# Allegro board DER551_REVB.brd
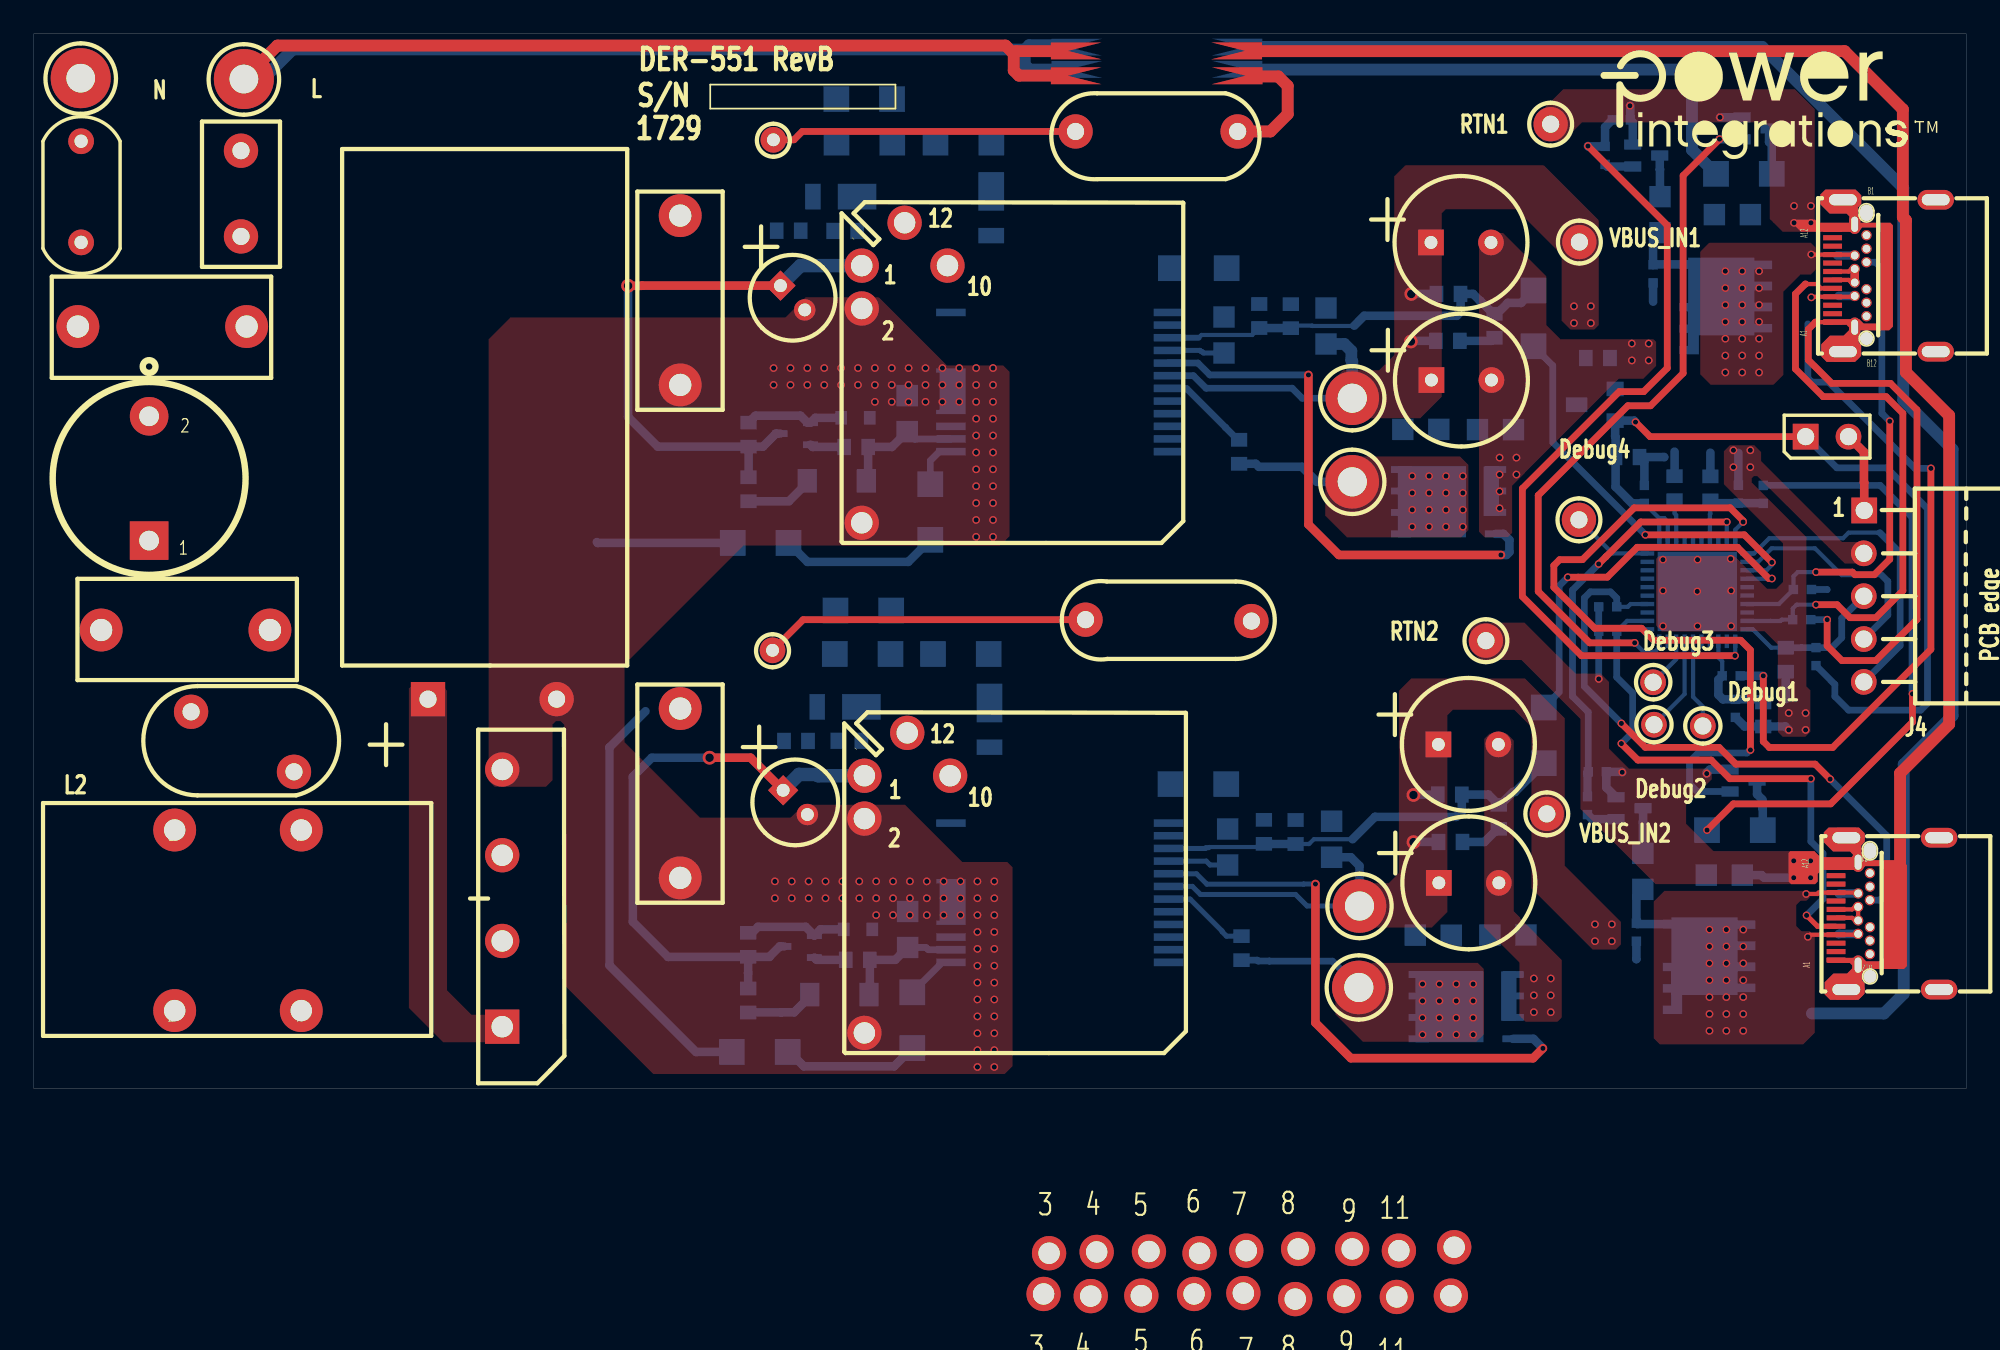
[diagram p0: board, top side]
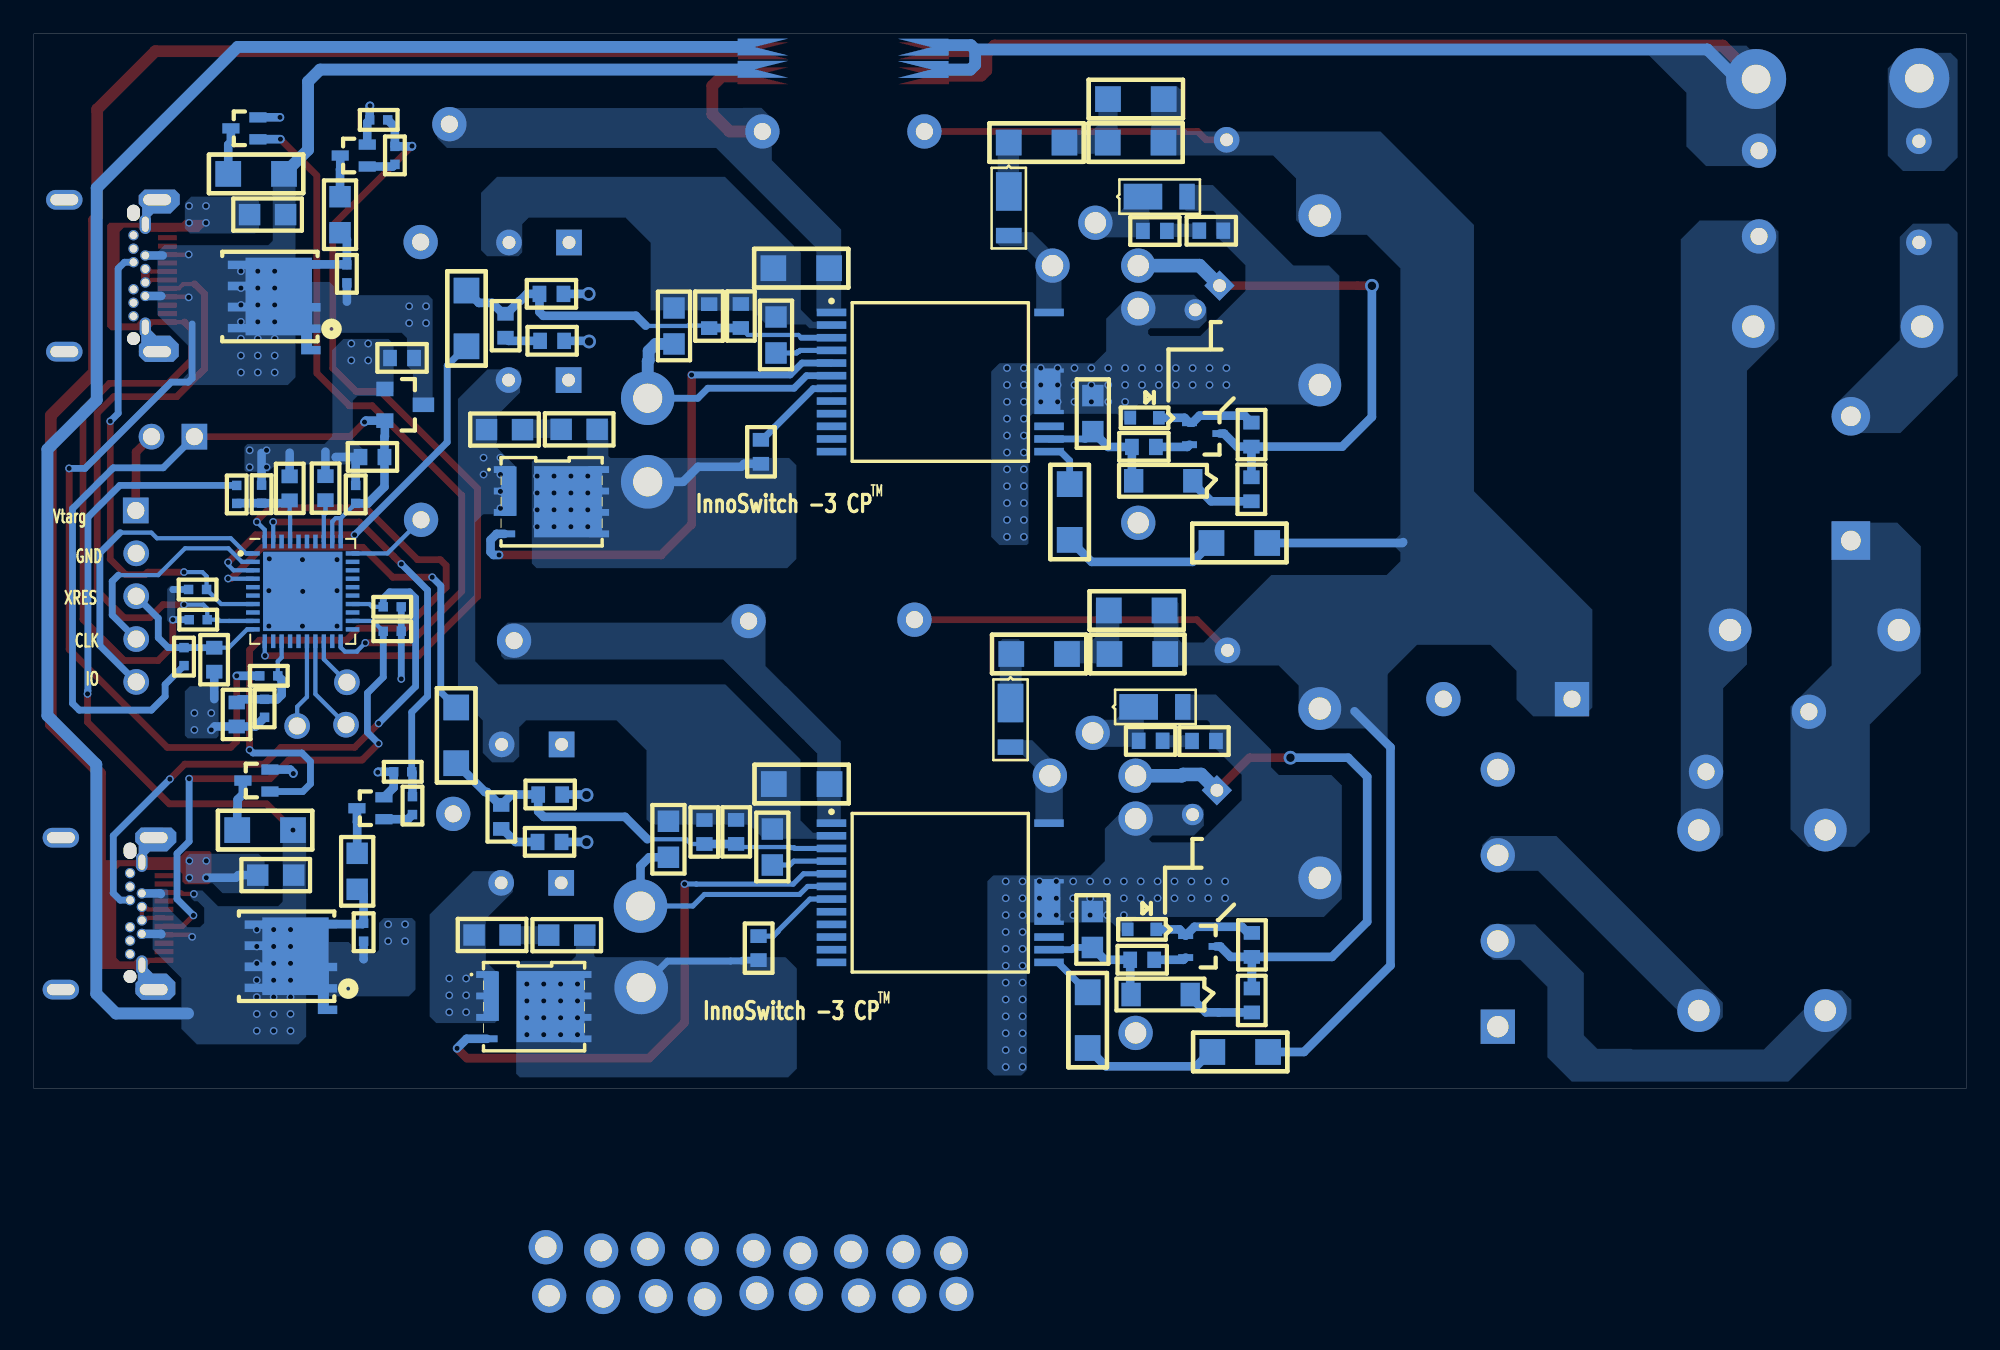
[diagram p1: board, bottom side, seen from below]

Outline 114.5 x 62.5 mm; copper layers: TOP, BOTTOM. Coordinates in mm from the lower left corner of the outline.
Outline path: 0,62.5 114.5,62.5 114.5,0 0,0 0,62.5

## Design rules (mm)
constraint set DEFAULT: min track width 0.508

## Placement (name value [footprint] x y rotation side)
BR1  GBL06  [PIDAXBRIDGEGBL06]  27.76 3.66 90 top
C1  1 nF  [PINPYCAPRAD540X290LS400040#2]  61.73 56.71 0 top
C2  470 uF  [PIPOLCAPCLYD320LS140030]  82.79 50.13 0 top
C3  470 uF  [PIPOLCAPCLYD320LS140030]  82.81 41.98 0 top
C4  2.2 nF  [PISMC1206]  50.85 58.63 180 bottom
C5  4.7 nF  [PISMC0603]  83.08 44.3 0 bottom
C6  1 nF  [PISMC0805]  85.54 39.04 0 bottom
C7  100 uF  [PIPOLCAPCLYD630LS300040]  23.36 23.07 0 top
C8  100 nF  [PI_NP_XCAP_RAD512X197X395D040]  38.3 51.72 270 top
C9  56 pF  [PISMC0603]  45.44 50.83 180 bottom
C10  100 nF  [PI_NP_CAP492X236LS394D040]  12.61 45.15 180 top
C11  2.2 uF  [PISMC0805]  70.52 45.72 270 bottom
C12  2.2 uF  [PISMC0805]  76.57 46.25 270 bottom
C13  100 nF  [PI_NP_CAP492X236LS394D040]  13.99 27.17 180 top
C14  22  uF  [PIPOLCAPCLYD200LS80030]  44.24 47.57 315 top
C15  330 pF  [PISMC0603]  72.61 45.06 90 bottom
C16  4.7 uF  [PISMC0805]  51.75 38.93 90 bottom
C17  1 nF  [PINPYCAPRAD540X290LS400040]  62.32 27.78 0 top
C18  470 uF  [PIPOLCAPCLYD320LS140030]  83.25 12.18 0 top
C19  470 uF  [PIPOLCAPCLYD320LS140030]  83.22 20.39 0 top
C20  2.2 nF  [PISMC1206]  50.8 28.33 180 bottom
C21  4.7 nF  [PISMC0603]  83.23 14.61 0 bottom
C22  1 nF  [PISMC0805]  86.28 9.1 0 bottom
C23  56 pF  [PISMC0603]  45.87 20.59 180 bottom
C24  100 nF  [PI_NP_XCAP_RAD512X197X395D040]  38.3 22.51 270 top
C25  2.2 uF  [PISMC0805]  70.74 15.38 270 bottom
C26  2.2 uF  [PISMC0805]  76.9 15.83 270 bottom
C27  22  uF  [PIPOLCAPCLYD200LS80030]  44.4 17.67 315 top
C28  330 pF  [PISMC0603]  72.89 14.49 90 bottom
C29  4.7 uF  [PISMC0805]  51.78 8.36 90 bottom
C30  1 uF  [PISMC0603]  91.97 43.29 0 bottom
C31  2.2 uF  [PISMC0603]  93.72 37.42 0 bottom
C32  100 nF  [PISMR0402]  95.43 34.67 90 bottom
C33  100 nF  [PISMC0603]  97.22 34.86 90 bottom
C34  100 nF  [PISMC0603]  102.47 22.87 270 bottom
C35  100 nF  [PISMC0603]  103.81 26.12 270 bottom
C36  330 pF  [PISMR0402]  104.26 29.57 0 bottom
C37  330 pF  [PISMR0402]  104.22 27.78 0 bottom
C38  330 pF  [PISMR0402]  93.79 28.54 180 bottom
C39  330 pF  [PISMR0402]  93.79 27.09 180 bottom
C40  100 nF  [PISMC0603]  99.34 34.85 90 bottom
C41  10 uF  [PISMC0805]  99.58 51.78 0 bottom
C42  10 uF  [PISMC0805]  99.1 12.64 0 bottom
D1  DFLR1600-7  [PISMDDFLR120012]  56.73 53.18 90 bottom
D2  DFLR1200-7  [PISMDDFLR120012]  48.81 52.85 0 bottom
D3  DFLR1600-7  [PISMDDFLR120012]  56.63 22.87 90 bottom
D4  DFLR1200-7  [PISMDDFLR120012]  49.06 22.61 0 bottom
F1  3.15 A  [PI_RST_MICROFUSE]  12.28 50.49 90 top
FL1  Hole_30mils  [PI_HOLE_30MIL]  43.82 56.22 0 top
FL2  Hole_70mils  [PI_HOLE_70MIL]  78.12 40.88 0 top
FL3  Hole_70mils  [PI_HOLE_70MIL]  78.12 35.92 0 top
FL4  Hole_30mils  [PI_HOLE_30MIL]  43.77 25.96 0 top
FL5  Hole_70mils  [PI_HOLE_70MIL]  78.55 10.79 0 top
FL6  Hole_70mils  [PI_HOLE_70MIL]  78.51 5.96 0 top
J1  USB-C/3.1  [PI_CONN_USB_3P1_TOP]  107.89 48.16 90 top
J2  USB-C/3.1  [PI_CONN_USB_3P1_TOP]  108.09 10.36 90 top
J3  CON2  [PIMOLEX2KKHEADER]  104.98 38.63 0 top
J4  CON5  [PI_MOLEX_5P_100_HEADER_RA]  108.43 24.09 90 top
L1  330 uh  [PI_CHOKE_RL5480-4_D2]  6.84 32.47 90 top
L2  12.5 mH  [PI_TOROID_CMC23X10P7_4P_V]  15.85 15.32 180 top
NOREF  -  []  -148.28 54.73 0 top
NOREF#2  -  []  -226.1 -144.28 0 top
NOREF#3  -  []  92.84 61.49 0 top
Q1  SIR876ADP-T1-GE3  [PISMPQFN5X6B]  86.61 36.67 270 bottom
Q2  MMST3904  [PISMSOT323132]  46.02 39.47 270 bottom
Q3  AON6403  [PI_DFN5X6_8L_EP1_P]  100.51 46.93 90 bottom
Q4  AON6403  [PI_DFN5X6_8L_EP1_P]  99.52 7.84 90 bottom
Q5  RJU003N03T106  [PISMSOT323]  94.74 55.93 90 bottom
Q6  RJU003N03T106  [PISMSOT323]  93.75 17.26 90 bottom
Q7  RJU003N03T106  [PISMSOT323]  101.22 57.54 90 bottom
Q8  RJU003N03T106  [PISMSOT323]  100.51 18.9 90 bottom
Q9  SIR876ADP-T1-GE3  [PISMPQFN5X6B]  87.65 6.75 270 bottom
Q10  MMST3904  [PISMSOT323132]  46.25 9.08 270 bottom
R1  205 k  [PISMR1206]  50.87 56.05 180 bottom
R2  5.6  [PISMR0805]  83.25 39.06 180 bottom
R3  100 k  [PISMR0603]  83.11 47.08 0 bottom
R4  14.7  [PISMR1206]  56.73 56.05 180 bottom
R5  1 k  [PISMR0603]  86.55 44.49 90 bottom
R6  22  [PISMR0603]  42.35 36.22 270 bottom
R7  100 k  [PISMR0603]  42.35 38.04 90 bottom
R8  100  [PISMR0603]  48.78 50.82 180 bottom
R9  47  [PISMR0603]  71.42 37.02 90 bottom
R10  2.00 M  [PISMR1206]  44.72 32.33 180 bottom
R11  3 k  [PISMR0603]  48.01 38.02 0 bottom
R12  34 k  [PISMR0603]  74.48 46.48 270 bottom
R13  2.00 M  [PISMR1206]  53.12 35.81 270 bottom
R14  31.6 k  [PISMR1206]  88.86 43.98 90 bottom
R15  0.011  [PISMR1206]  70.68 48.61 180 bottom
R16  49.9 k  [PISMR0402]  95.95 47.74 90 bottom
R17  49.9 k  [PISMR0402]  94.96 8.73 90 bottom
R18  1.00 k  [PISMR0805]  96.35 50.71 90 bottom
R19  200  [PISMR1206]  99.68 54.2 0 bottom
R20  1.00 k  [PISMR0805]  95.34 11.8 90 bottom
R21  200  [PISMR1206]  99.14 15.31 0 bottom
R22  10  [PISMR0402]  93.1 55.83 270 bottom
R23  10  [PISMR0402]  92.06 17.3 270 bottom
R24  100.0 k  [PISMR0402]  93.53 57.4 0 bottom
R25  100.0 k  [PISMR0402]  92.11 18.77 0 bottom
R26  205 k  [PISMR1206]  50.76 25.75 180 bottom
R27  5.6  [PISMR0805]  83.99 9.09 180 bottom
R28  100 k  [PISMR0603]  83.19 17.42 0 bottom
R29  14.7  [PISMR1206]  56.58 25.75 180 bottom
R30  1 k  [PISMR0603]  86.8 15.38 90 bottom
R31  22  [PISMR0603]  42.33 5.93 270 bottom
R32  100 k  [PISMR0603]  42.33 7.8 90 bottom
R33  100  [PISMR0603]  49.04 20.6 180 bottom
R34  47  [PISMR0603]  71.56 7.6 90 bottom
R35  2.00 M  [PISMR1206]  44.67 2.16 180 bottom
R36  2.00 M  [PISMR1206]  52.06 5.7 270 bottom
R37  3 k  [PISMR0603]  48.11 7.62 0 bottom
R38  34 k  [PISMR0603]  74.76 15.91 270 bottom
R39  31.6 k  [PISMR1206]  89.47 22.58 270 bottom
R40  0.011  [PISMR1206]  70.65 18.04 180 bottom
R41  100K 1%  [PISMR0402]  101.11 24.45 180 bottom
R42  10.0 k  [PISMR0402]  100.82 23.06 270 bottom
R43  4.7 k  [PISMR0402]  105.6 25.06 90 bottom
R44  100K 1%  [PISMR0402]  102.47 35.73 270 bottom
R45  10.0 k  [PISMR0402]  101 34.68 90 bottom
RT1  2.5  [PI_RAD180X395LS235D031]  2.8 56.13 270 top
RV1  300 Vac  [PIDISC350X225LS240X140040]  9.32 22.32 0 top
T1  RM8  [PI_BOBBIN_RM8_12P_CLP]  49.06 48.76 180 top
T2  RM8  [PI_BOBBIN_RM8_12P_CLP#2]  49.22 18.53 180 top
TP1  WHT  [PITPKEYSTONE125X125]  2.78 59.87 0 top
TP2  BLK  [PITPKEYSTONE125X125]  12.45 59.82 0 top
TP3  RED  [PITPKEYSTONE100X100]  91.58 50.16 0 top
TP4  BLK  [PITPKEYSTONE100X100]  89.88 57.14 0 top
TP5  RED  [PITPKEYSTONE100X100]  89.65 16.27 0 top
TP6  BLK  [PITPKEYSTONE100X100]  86.04 26.53 0 top
TP7  BLUE  [PITPKEYSTONE100X100]  98.89 21.48 0 top
TP8  WHT  [PITPKEYSTONE100X100]  96 21.56 0 top
TP9  BLUE  [PITPKEYSTONE100X100]  95.95 24.07 0 top
TP10  WHT  [PITPKEYSTONE100X100]  91.55 33.7 0 top
U1  INN3266C-H210  [PI_IC_INSOP_24D]  67.23 45.99 180 bottom
U2  INN3266C-H210  [PI_IC_INSOP_24D]  67.23 15.72 180 bottom
U3  AP2210N-3.3TRG1  [PISMSOT23132]  93.7 39.57 270 bottom
U4  CYPD4225-40LQXIT  [QFN50P600X600X60-41T470X470N]  98.56 29.46 180 bottom
VR1  MMSZ5256B-7-F  [PI_SM_SOD-123_12]  45.83 36.01 0 bottom
VR2  DZ2S100M0L  [PI_SM_D_SSMINI2P]  47.84 39.74 0 bottom
VR3  MMSZ5256B-7-F  [PI_SM_SOD-123_12]  45.98 5.57 0 bottom
VR4  DZ2S100M0L  [PI_SM_D_SSMINI2P]  47.99 9.43 0 bottom

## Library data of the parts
BR1 = DISCRETE BRIDGE_+~~-
C1 C17 = CAP NP: alternate symbols: (pinpycaprad540x290ls400040h,pinpycaprad500x220ls400040)
C2 C3 C18 C19 = CAP POL: alternate symbols: (pipolcapclyd320ls140030430h)
C4-C6 C8-C13 C15 C16 C20-C26 C28-C42 = CAP NP
C7 = CAP POL: alternate symbols: (pipolcapclyd630ls3000401120h)
C14 C27 = CAP POL: alternate symbols: (pipolcapclyd200ls80030h)
D1-D4 = DIODE
F1 = FUSE: alternate symbols: (pirstmicrofusehoz)
FL1-FL6 = FlyingLead
J1 J2 = CON24_USB: alternate symbols: (pi_conn_usb_3p1_topD)
J3 = CON2
J4 = CON5
L1 = INDUCTOR_DOT2: alternate symbols: (pi_choke_RL5480-4H_d2)
L2 = TORRID 4P_14_23
Q1 Q9 = FET_N_SGD_123_4_5678
Q2 Q10 = NPN_BEC
Q3 Q4 = FET_P_SSSGDDDD
Q5-Q8 = FET_N_SGD
R1-R45 = R
RT1 = THERMISTOR: alternate symbols: (pirad550x410ls300040_h)
RV1 = VARISTOR
T1 T2 = BRM8_12P_CLP: alternate symbols: (pi_bobbin_rm8_12p_clp)
TP1-TP10 = TESTPOINT
U1 U2 = Inno3CP
U3 = AP2210N
U4 = CYPD4225
VR1-VR4 = DIODE_ZENER

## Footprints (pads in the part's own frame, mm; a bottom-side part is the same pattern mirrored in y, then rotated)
PI_BOBBIN_RM8_12P_CLP
  round 2.032 hole 1.27: 1(0,0) 2(0,2.54) 3(-11.1,58.522) 4(-13.919,58.445) 5(-17.018,58.42) 6(-20.015,58.522) 7(-22.784,58.369) 8(-25.857,58.268) 9(-29.058,58.268) 10(-5.08,0) 11(-31.826,58.369) 12(-2.54,-2.54) CLP1(-35.103,58.166) CLP2(0,15.24)
PI_BOBBIN_RM8_12P_CLP#2
  round 2.032 hole 1.27: 1(0,0) 2(0,2.54) 3(-10.617,30.709) 4(-13.411,30.836) 5(-16.408,30.81) 6(-19.533,30.709) 7(-22.454,30.658) 8(-25.527,31.013) 9(-28.423,30.836) 10(-5.08,0) 11(-31.547,30.886) 12(-2.54,-2.54) CLP1(-34.747,30.81) CLP2(0,15.24)
PI_CHOKE_RL5480-4_D2
  rect 2.286x2.286 hole 1.168: 1(0,0)
  round 2.286 hole 1.168: 2(7.366,0)
PI_CONN_USB_3P1_TOP
  oval 1.168x2.159 hole 0.66x1.651: (-4.5,0.7) (-4.5,-4.8) (4.5,0.7) (4.5,-4.8)
  round 0.762 hole 0.762: (-3.725,-0.7)
  oval 0.965x0.762 hole 0.965x0.762 unplated: (3.725,-0.7)
  rect 0.305x1.118 smd: A1(-2.75,1.31) A2(-2.25,1.31) A3(-1.75,1.31) A4(-1.25,1.31) A5(-0.75,1.31) A6(-0.25,1.31) A7(0.25,1.31) A8(0.75,1.31) A9(1.25,1.31) A10(1.75,1.31) A11(2.25,1.31) A12(2.75,1.31)
  oval 1.15x0.66 hole 0.9x0.406: B1(3.05,0) B12(-3.05,0)
  round 0.61 hole 0.457: B2(2.4,-0.7) B3(1.6,-0.7) B4(1.2,0) B5(0.8,-0.7) B6(0.4,0) B7(-0.4,0) B8(-0.8,-0.7) B9(-1.2,0) B10(-1.6,-0.7) B11(-2.4,-0.7)
PI_DFN5X6_8L_EP1_P
  custom 0.288x0.288 smd: 1(-1.905,-2.425)
  custom 0.125x0.125 smd: 4(1.905,-2.425)
  custom 1.15x1.15 smd: 7(0,0)
PI_HOLE_30MIL
  round 1.524 hole 0.762: 1(0,0)
PI_HOLE_70MIL
  round 3.175 hole 1.727: 1(0,0.025)
PI_IC_INSOP_24D
  rect 1.75x0.45 smd: 1(0,0) 2(0,-0.75) 3(0,-1.5) 4(0,-2.25) 5(0,-3) 6(0,-3.75) 7(0,-4.5) 8(0,-5.25) 9(0,-6) 10(0,-6.75) 11(0,-7.5) 12(0,-8.25) 13(12.89,-8.25) 14(12.89,-7.5) 15(12.89,-6.75) 24(12.89,0)
  custom 0.438x0.438 smd: 16(12.89,-4.67)
PI_MOLEX_5P_100_HEADER_RA
  rect 1.524x1.524 hole 1.016: 1(10.16,-0.025)
  round 1.524 hole 1.016: 2(7.62,0) 3(5.08,0) 4(2.54,0) 5(0,0)
PI_NP_CAP492X236LS394D040
  round 2.54 hole 1.321: 1(0,0) 2(10,0)
PI_NP_XCAP_RAD512X197X395D040
  round 2.54 hole 1.321: 1(0,0) 2(10.033,0)
PI_RAD180X395LS235D031
  round 1.524 hole 0.787: 1(0,0) 2(5.994,0)
PI_RST_MICROFUSE
  round 2.032 hole 1.016: 1(0,0) 2(5.08,0)
PI_SM_D_SSMINI2P
  rect 0.699x0.8 smd: 1(0,0) 2(1.7,0)
PI_SM_SOD-123_12
  rect 1.143x1.397 smd: 1(0,0) 2(3.505,0)
PI_TOROID_CMC23X10P7_4P_V
  round 2.54 hole 1.27: 1(0,0) 2(7.5,0) 3(7.5,10.7) 4(0,10.7)
PIDAXBRIDGEGBL06
  rect 2.032x2.032 hole 1.27: 1(0,0)
  round 2.032 hole 1.27: 2(5.08,0) 3(10.16,0) 4(15.24,0)
PIDISC350X225LS240X140040
  round 2.032 hole 1.016: 1(0,0) 2(6.096,-3.556)
PIMOLEX2KKHEADER
  rect 1.524x1.524 hole 1.016: 1(0,0)
  round 1.524 hole 1.016: 2(2.54,0)
PINPYCAPRAD540X290LS400040
  round 2.032 hole 1.016: 1(0,0) 2(9.83,-0.083)
PINPYCAPRAD540X290LS400040#2
  round 2.032 hole 1.016: 1(0,0) 2(9.601,0)
PIPOLCAPCLYD200LS80030
  rect 1.27x1.27 hole 0.762: 1(0,0)
  round 1.27 hole 0.762: 2(2.032,0)
PIPOLCAPCLYD320LS140030
  rect 1.524x1.524 hole 0.762: 1(0,0)
  round 1.524 hole 0.762: 2(3.556,0)
PIPOLCAPCLYD630LS300040
  rect 2.032x2.032 hole 1.016: 1(0,0)
  round 2.032 hole 1.016: 2(7.62,0)
PISMC0603
  rect 0.813x0.965 smd: 1(0,0) 2(1.422,0)
PISMC0805
  rect 1.27x1.27 smd: 1(0,0) 2(2.134,0)
PISMC1206
  rect 1.524x1.524 smd: 1(0,0) 2(3.302,0)
PISMDDFLR120012
  rect 2.286x1.524 smd: 1(-0.025,0)
  rect 0.914x1.524 smd: 2(-2.642,0)
PISMPQFN5X6B
  rect 0.406x1.27 smd: 1(0,0) 2(1.27,0) 3(2.54,0) 4(3.81,0)
  rect 0.406x1.219 smd: 5(3.81,5.588) 6(2.54,5.588) 7(1.27,5.588) 8(0,5.588)
PISMR0402
  rect 0.559x0.559 smd: 1(0,0) 2(1.067,0)
PISMR0603
  rect 0.813x0.965 smd: 1(0,0) 2(1.422,0)
PISMR0805
  rect 1.27x1.27 smd: 1(0,0) 2(2.134,0)
PISMR1206
  rect 1.524x1.524 smd: 1(0,0) 2(3.302,0)
PISMSOT323
  rect 0.61x1.016 smd: 1(0,0) 2(-1.3,0) 3(-0.65,1.6)
PISMSOT23132
  rect 0.864x1.016 smd: 1(-1.88,0) 2(0,0)
  rect 0.864x1.27 smd: 3(-0.94,2.286)
PISMSOT323132
  rect 0.406x0.889 smd: 1(0.018,0) 2(1.321,0) 3(0.66,1.803)
PITPKEYSTONE100X100
  round 2.032 hole 1.016: 1(0,0)
PITPKEYSTONE125X125
  round 3.556 hole 1.702: 1(0,0)
QFN50P600X600X60-41T470X470N
  rect 0.81x0.26 smd: 1(-2.955,2.25) 2(-2.955,1.75) 3(-2.955,1.25) 4(-2.955,0.75) 5(-2.955,0.25) 6(-2.955,-0.25) 7(-2.955,-0.75) 8(-2.955,-1.25) 9(-2.955,-1.75) 10(-2.955,-2.25) 21(2.955,-2.25) 22(2.955,-1.75) 23(2.955,-1.25) 24(2.955,-0.75) 25(2.955,-0.25) 26(2.955,0.25) 27(2.955,0.75) 28(2.955,1.25) 29(2.955,1.75) 30(2.955,2.25)
  rect 0.26x0.81 smd: 11(-2.25,-2.955) 12(-1.75,-2.955) 13(-1.25,-2.955) 14(-0.75,-2.955) 15(-0.25,-2.955) 16(0.25,-2.955) 17(0.75,-2.955) 18(1.25,-2.955) 19(1.75,-2.955) 20(2.25,-2.955) 31(2.25,2.955) 32(1.75,2.955) 33(1.25,2.955) 34(0.75,2.955) 35(0.25,2.955) 36(-0.25,2.955) 37(-0.75,2.955) 38(-1.25,2.955) 39(-1.75,2.955) 40(-2.25,2.955)
  rect 4.7x4.7 smd: 41(0,0)

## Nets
GND: C2.2 C3.2 C6.2 C11.1 C12.1 C15.2 C18.2 C19.2 C22.2 C25.1 C26.1 C28.2 C30.2 C31.2 C32.2 C33.2 C34.2 C35.2 C40.2 J4.2 Q1.1 Q1.2 Q1.3(S3) Q9.1 Q9.2 Q9.3(S3) R12.1 R15.1 R38.1 R40.1 R42.2 R45.2 U1.2 U2.2 U3.1 U4.41
GND1: BR1.4 C7.2 C8.2 C9.2 C14.2 C16.2 C23.2 C24.2 C27.2 C29.2 D2.2 D4.2 T1.2 T1.CLP2 T2.2 T2.CLP2 U1.16 U2.16 VR2.2 VR4.2
VBUS_DISCHARGE_P1: Q7.2 U4.20
VBUS_DISCHARGE_P2: Q8.2 U4.40
VBUS_IN_1: C2.1 C3.1 C5.1 C12.2 C30.1 FL2.1 Q3.1(S1) R3.1 R16.1 TP3.1 U1.6 U3.3
VBUS_IN_2: C18.1 C19.1 C21.1 C26.2 FL5.1 Q4.1(S1) R17.1 R28.1 TP5.1 U2.6
VBUS_OUT_1: C41.1 J1.A4 J1.A9 J1.B4 J1.B9(VBUS4) Q3.7 R19.1 R41.1
VBUS_OUT_2: C42.1 J2.A4 J2.A9 J2.B4 J2.B9(VBUS4) Q4.7 R21.1 R44.1
VBUS_P_CTRL_P1: R22.1 R24.1 U4.11
VBUS_P_CTRL_P2: R23.1 R25.1 U4.39
VDD_SUPPLY: C31.1 C32.1 J3.1 R43.1 U3.2(OUT) U4.31 U4.32
CC1_P1: C37.1 J1.A5 U4.9
CC1_P2: C39.1 J2.A5 U4.22
CC2_P1: C36.1 J1.B5 U4.7
CC2_P2: C38.1 J2.B5 U4.24
CLK: J4.4 U4.2
D: FL6.1 Q9.5 Q9.6 Q9.7 Q9.8 R27.2 R34.1
D+_1: J1.A6 J1.A7 J1.B6 J1.B7
D+_2: J2.A6 J2.A7 J2.B6 J2.B7
D_2245090: FL3.1 Q1.5 Q1.6 Q1.7 Q1.8 R2.2 R9.1
DEBUG_1: TP7.1 U4.16
DEBUG_2: TP8.1 U4.17
DEBUG_3: TP9.1 U4.18
DEBUG_4: TP10.1 U4.30
IO: J4.5 U4.1
NC8: U1.8 U2.8
NC9: U1.9 U2.9
NC10: U1.10 U2.10
NC11: U1.11 U2.11
NC12: U1.12 U2.12
NC15: U1.15 U2.15
POW1: BR1.1 C1.1 C4.2 C7.1 C8.1 C17.1 C20.2 C24.1 FL1.1 FL4.1 R1.2 R10.2 R26.2 R35.2
RTN1: C1.2 C36.2 C37.2 C41.2 J1.A1 J1.A12 J1.B1 J1.B12 Q5.1(S) Q7.1(S) R15.2 R24.2 TP4.1 U1.1
RTN2: C17.2 C38.2 C39.2 C42.2 J2.A1 J2.A12 J2.B1 J2.B12 Q6.1(S) Q8.1(S) R25.2 R40.2 TP6.1 U2.1
VSEL_1_P1: R14.1 U4.3
VSEL_1_P2: R39.1 U4.4
VTARG: J3.2 J4.1
XRES: C35.1 J4.3 R43.2 U4.10(XRES)
N2239928: D1.2 T1.10 U1.24
N2254675: C4.1 R1.1 R4.2
N2276765: C16.1 R11.2 U1.14 VR1.2
N2494768: C14.1 Q2.3 R6.1 R7.1 T1.1
N2642535: Q2.2(EMITTER) R11.1
N2666518: R9.2 U1.7
N2722737: C6.1 R2.1
N2725054: D2.1 R8.1 T1.12
N2729570: Q1.4 U1.5
N2736973: C15.1 R3.2 R5.2 R12.2 R14.2 U1.3
N2741729: D1.1 R4.1
N2742169: Q2.1 R7.2 VR2.1
N2993205: R6.2 VR1.1
N2996861: C5.2 R5.1
N4181205: R10.1 R13.2
N4181233: R13.1 U1.13(VPIN)
N11315036: Q4.4 R17.2 R20.1
N11315198: Q6.3 R20.2
N11315244: Q8.3 R21.2
N11315300: Q6.2 R23.2
N11318075: Q3.4 R16.2 R18.1
N11318137: Q7.3 R19.2
N11318145: Q5.3 R18.2
N11318201: Q5.2 R22.2
N11323189: C27.1 Q10.3 R31.1 R32.1 T2.1
N11323399: D3.2 T2.10 U2.24
N11323505: C22.1 R27.1
N11323517: C21.2 R30.1
N11323551: C20.1 R26.1 R29.2
N11323577: D4.1 R33.1 T2.12
N11323649: D3.1 R29.1
N11323661: C28.1 R28.2 R30.2 R38.2 R39.2 U2.3
N11323821: Q9.4 U2.5
N11323873: R31.2 VR3.1
N11323885: Q10.1 R32.2 VR4.1
N11323925: R34.2 U2.7
N11323959: Q10.2(EMITTER) R37.1
N11324073: C29.1 R37.2 U2.14 VR3.2
N11324349: R36.1 U2.13(VPIN)
N11338172: R35.1 R36.2
N11773410: F1.2 TP2.1
N11773414: RT1.1 TP1.1
N11773458: C10.1 C13.1 F1.1 L2.1 RV1.2
N11773490: C13.2 L1.1 L2.2 RV1.1
N11773520: BR1.3(AC2) L2.4
N11773524: BR1.2 L2.3
N11791704: C34.1 R41.2 R42.1 U4.13
N11792407: C40.1 R44.2 R45.1 U4.37
N11794782: C33.1 U4.33
N11800517: C10.2 L1.2 RT1.2
N11809700: C11.2 U1.4
N11811366: C25.2 U2.4
N27250240: C9.1 R8.2
N113238491: C23.1 R33.2

Pads without a net: J1 A2 A3 A8 A10 A11 B2 B3 B8 B10 B11; J2 A2 A3 A8 A10 A11 B2 B3 B8 B10 B11; T1 3 4 5 6 7 8 9 11 CLP1; T2 3 4 5 6 7 8 9 11 CLP1; U4 5 6 8 12 14 15 19 21 23 25 26 27 28 29 34 35 36 38

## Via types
v1: diameter 0.457, hole 0.305, TOP to BOTTOM, 268 vias
v2: diameter 0.813, hole 0.508, TOP to BOTTOM, 6 vias

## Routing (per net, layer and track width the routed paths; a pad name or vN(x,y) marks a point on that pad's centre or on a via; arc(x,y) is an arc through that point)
GND: length 13.1
  BOTTOM w0.508: C32.2 95.43,37.13 C31.2 96.6,37.42 96.61,37.41 ; C40.2 99.34,37.67 ; v1(103.98,21.25) 103.78,21.45 C34.2 101.36,21.45 R42.2 ; R45.2 101,37.66 ; C33.2 97.22,37.74 ; C35.2 103.81,23.07
  vias: v1(86.85,37.38) v1(86.85,36.38) v1(86.85,35.38) v1(86.85,34.38) v1(87.85,37.38) v1(87.85,36.38) v1(88.88,6.52) v1(88.88,5.52) v1(88.88,4.52) v1(89.88,6.52) v1(89.88,5.52) v1(89.88,4.52) v1(94.69,44.14) v1(94.69,43.14) v1(95.69,44.14) v1(95.69,43.14) v1(96.53,31.34) v1(96.53,29.5) v1(96.53,27.4) v1(98.58,31.34) v1(98.56,29.46) v1(98.58,27.4) v1(100.54,31.39) v1(100.57,29.5) v1(100.57,27.4) v1(100.71,37.82) v1(100.71,36.82) v1(101.71,37.82) v1(101.71,36.82) v1(103.98,22.25) v1(104.98,22.25) v1(104.98,21.25)
GND1:
  vias: v1(43.84,42.69) v1(43.84,41.69) v1(43.91,12.27) v1(43.91,11.27) v1(44.84,42.69) v1(44.84,41.69) v1(44.91,12.27) v1(44.91,11.27) v1(45.84,42.69) v1(45.84,41.69) v1(45.91,12.27) v1(45.91,11.27) v1(46.84,42.69) v1(46.84,41.69) v1(46.91,12.27) v1(46.91,11.27) v1(47.84,42.69) v1(47.84,41.69) v1(47.91,12.27) v1(47.91,11.27) v1(48.84,42.69) v1(48.84,41.69) v1(48.91,12.27) v1(48.91,11.27) v1(49.84,42.69) v1(49.84,41.69) v1(49.84,40.69) v1(49.91,12.27) v1(49.91,11.27) v1(49.91,10.27) v1(50.84,42.69) v1(50.84,41.69) v1(50.84,40.69) v1(50.91,12.27) v1(50.91,11.27) v1(50.91,10.27) v1(51.84,42.69) v1(51.84,41.69) v1(51.84,40.69) v1(51.91,12.27) v1(51.91,11.27) v1(51.91,10.27) v1(52.84,42.69) v1(52.84,41.69) v1(52.84,40.69) v1(52.91,12.27) v1(52.91,11.27) v1(52.91,10.27) v1(53.84,42.69) v1(53.84,41.69) v1(53.84,40.69) v1(53.91,12.27) v1(53.91,11.27) v1(53.91,10.27) v1(54.84,42.69) v1(54.84,41.69) v1(54.84,40.69) v1(54.91,12.27) v1(54.91,11.27) v1(54.91,10.27) v1(55.84,42.69) v1(55.84,41.69) v1(55.84,40.69) v1(55.84,39.69) v1(55.84,38.69) v1(55.84,37.69) v1(55.84,36.69) v1(55.84,35.69) v1(55.84,34.69) v1(55.84,33.69) v1(55.84,32.69) v1(55.91,12.27) v1(55.91,11.27) v1(55.91,10.27) v1(55.91,9.27) v1(55.91,8.27) v1(55.91,7.27) v1(55.91,6.27) v1(55.91,5.27) v1(55.91,4.27) v1(55.91,3.27) v1(55.91,2.27) v1(55.91,1.27) v1(56.84,42.69) v1(56.84,41.69) v1(56.84,40.69) v1(56.84,39.69) v1(56.84,38.69) v1(56.84,37.69) v1(56.84,36.69) v1(56.84,35.69) v1(56.84,34.69) v1(56.84,33.69) v1(56.84,32.69) v1(56.91,12.27) v1(56.91,11.27) v1(56.91,10.27) v1(56.91,9.27) v1(56.91,8.27) v1(56.91,7.27) v1(56.91,6.27) v1(56.91,5.27) v1(56.91,4.27) v1(56.91,3.27) v1(56.91,2.27) v1(56.91,1.27)
VBUS_DISCHARGE_P1: length 42.5
  TOP w0.4: v1(99.88,56.25) 97.72,54.09 97.72,42.38 95.79,40.45 94.45,40.45 89.14,35.15 89.14,29.46 92.19,26.41 v1(94.85,26.41)
  BOTTOM w0.25: v1(94.85,26.41) 95.34,25.93 95.34,25.89 96.06,25.89 96.31,26.14 U4.20
  BOTTOM w0.508: Q7.2 101.21,56.25 v1(99.88,56.25)
VBUS_DISCHARGE_P2: length 42.6
  TOP w0.4: v1(101.71,20.06) 101.71,25.98 101.13,26.56 95.97,26.56 95.26,27.27 92.49,27.27 90.07,29.7 90.07,30.99 90.41,31.34 91.76,31.34 94.83,34.41 100.51,34.41 101.28,33.64 v1(101.28,33.57)
  BOTTOM w0.25: U4.40 100.81,33.1 v1(101.28,33.57)
  BOTTOM w0.4: Q8.2 98.56,17.6 98.11,18.05 98.11,19.37 98.61,19.88 101.51,19.88 101.69,20.06 v1(101.71,20.06)
VBUS_IN_1: length 20
  BOTTOM w0.4: FL2.1 75.15,40.9 74.56,41.5 69.45,41.5 68.71,42.24 U1.6
  BOTTOM w0.508: R16.1 95.95,46.63 ; R3.1 81.62,47.08 v2(81.62,47.08) ; v2(81.6,44.26) 81.63,44.3 C5.1
  BOTTOM w0.7: FL2.1 78.12,43.09 78.06,43.15 78.06,43.71 77.65,44.12 C12.2
  vias: v1(91.26,46.35) v1(91.26,45.35) v1(92.26,46.35) v1(92.26,45.35)
VBUS_IN_2: length 20
  BOTTOM w0.3: FL5.1 75.45,10.81 74.76,11.5 69.12,11.5 68.65,11.97 U2.6
  BOTTOM w0.508: FL5.1 78.55,13.19 78.04,13.7 C26.2 ; R28.1 81.77,17.42 v2(81.75,17.39) ; C21.1 81.76,14.61 v2(81.75,14.6) ; 94.96,7.67 R17.1
  vias: v1(92.5,9.73) v1(92.5,8.73) v1(93.5,9.73) v1(93.5,8.73)
VBUS_OUT_1: length 80.8
  TOP w0.25: J1.B4 107.84,49.41 J1.A9 105.33,49.41 v1(105.32,49.42) ; v1(105.32,46.88) 105.35,46.91 J1.A4 107.84,46.91 J1.B9
  TOP w0.4: v1(102.47,24.45) 102.47,20.57 102.83,20.21 106.59,20.21 112.41,26.03 v1(112.41,36.75)
  BOTTOM w0.4: v1(112.41,36.75) 111.46,36.75 106.35,41.86 105.34,41.86 105.12,42.08 105.12,45.31
  BOTTOM w0.508: J1.B9 106.95,46.96 ; R41.1 101.67,24.45 v1(102.47,24.45) ; J1.B4 106.86,49.36
  BOTTOM w0.7: 72.19,60.38 97.54,60.38 98.25,59.66 98.25,55.62 R19.1
  vias: v1(100.23,48.43) v1(100.23,47.43) v1(100.23,46.43) v1(100.23,45.43) v1(100.23,44.43) v1(100.23,43.43) v1(100.23,42.43) v1(101.23,48.43) v1(101.23,47.43) v1(101.23,46.43) v1(101.23,45.43) v1(101.23,44.43) v1(101.23,43.43) v1(101.23,42.43) v1(102.23,48.43) v1(102.23,47.43) v1(102.23,46.43) v1(102.23,45.43) v1(102.23,44.43) v1(102.23,43.43) v1(102.23,42.43)
VBUS_OUT_2: length 143.1
  TOP w0.25: v1(105.01,11.53) 105.67,11.53 105.76,11.61 J2.A9 108.04,11.61 J2.B4 ; v1(105.12,8.99) 105.24,9.11 J2.A4 108.04,9.11 J2.B9
  TOP w0.4: v1(111.31,23.39) 111.31,21.71 106.47,16.87 100.7,16.87 v1(99.14,15.31)
  BOTTOM w0.4: v1(111.31,23.39) 111.31,23.54 111.29,23.56 111.29,33.85 109.4,35.73 R44.1
  BOTTOM w0.508: J2.B9 106.97,9.16 106.94,9.14 ; J2.B4 107.01,11.56 106.97,11.52
  BOTTOM w0.7: 105.36,4.45 109.63,4.45 110.79,5.61 110.79,19.2 113.69,22.1 113.69,37.87 110.77,40.79 110.77,53.37 102.41,61.72 72.24,61.72
  vias: v1(99.29,9.42) v1(99.29,8.42) v1(99.29,7.42) v1(99.29,6.42) v1(99.29,5.42) v1(99.29,4.42) v1(99.29,3.42) v1(100.29,9.42) v1(100.29,8.42) v1(100.29,7.42) v1(100.29,6.42) v1(100.29,5.42) v1(100.29,4.42) v1(100.29,3.42) v1(101.29,9.42) v1(101.29,8.42) v1(101.29,7.42) v1(101.29,6.42) v1(101.29,5.42) v1(101.29,4.42) v1(101.29,3.42)
VBUS_P_CTRL_P1: length 50.7
  TOP w0.4: v1(100.8,25.65) 91.7,25.65 88.2,29.15 88.2,35.55 93.94,41.29 95.39,41.29 96.78,42.69 96.78,51.15 v1(92.09,55.85)
  BOTTOM w0.25: U4.11 100.81,25.66 v1(100.8,25.65)
  BOTTOM w0.508: v1(92.09,55.85) 92.11,55.83 R22.1 93.1,56.97 R24.1
VBUS_P_CTRL_P2: length 24.6
  TOP w0.4: v1(92.72,31.08) 93.15,31.51 93.15,31.51 95.21,33.57 v1(100.31,33.57)
  BOTTOM w0.25: U4.39 v1(100.31,33.57)
  BOTTOM w0.4: v1(92.72,31.08) 91.17,29.53 91.17,23.24 92.11,22.3 R25.1
  BOTTOM w0.508: R25.1 92.06,18.72 R23.1
VDD_SUPPLY: length 50.9
  TOP w0.4: J3.1 95.77,38.63 v1(94.91,39.49)
  BOTTOM w0.25: 96.31,33.79 96.33,33.8 96.61,33.8 96.81,33.59 U4.32 ; 96.31,33.79 U4.31 ; 96.31,33.79 C32.1
  BOTTOM w0.4: J3.1 106.83,36.78 109.78,36.78 112.2,34.36 112.2,22.82 111.8,22.42 107.53,22.42 106.72,23.23 106.72,23.94 R43.1
  BOTTOM w0.508: v1(94.91,39.49) 94.82,39.57 U3.2 93.7,38.63 93.72,38.61 C31.1 93.72,35.65 94.7,34.67 C32.1
CC1_P1: length 36
  TOP w0.25: 104.99,47.67 105.65,47.67 105.9,47.41 J1.A5
  TOP w0.4: v1(105.6,28.67) 106.84,28.67 107.61,27.9 109.15,27.9 110.74,29.5 110.74,40.01 109.75,41 106.02,41 104.38,42.64 104.38,47.08 104.96,47.67 104.99,47.67
  BOTTOM w0.25: U4.9 102.93,27.71 102.93,27.7 103.49,27.7 103.56,27.78 C37.1 104.22,28.44 104.45,28.67 v1(105.6,28.67)
CC1_P2: length 32.3
  TOP w0.3: v1(105.04,10.26) 105.69,9.61 J2.A5
  TOP w0.4: v1(94.07,20.44) 95.04,19.46 99.39,19.46 100.49,18.36 v1(105.29,18.36)
  BOTTOM w0.25: C39.1 94.4,27.71 U4.22
  BOTTOM w0.4: v1(105.29,18.36) 105.29,14.64 106.01,13.92 106.01,11.23 v1(105.04,10.26) ; v1(94.07,20.44) 94.73,21.1 94.73,23.43 93.79,24.37 C39.1
CC2_P1: length 28.6
  TOP w0.4: v1(109.97,39.54) 109.97,31.36 109.05,30.44 107.9,30.44 107.75,30.6 v1(105.6,30.6)
  BOTTOM w0.25: v1(105.6,30.6) 104.51,30.6 104.26,30.35 C36.1 103.4,28.71 U4.7
  BOTTOM w0.4: v1(109.97,39.54) 109.5,40.01 109.5,48.58 109.12,48.96 J1.B5
CC2_P2: length 36
  TOP w0.4: v1(106.44,18.33) 105.55,19.22 100.85,19.22 99.85,20.21 95.49,20.21 v1(94.07,21.63)
  BOTTOM w0.25: U4.24 94.62,28.71 94.45,28.54 C38.1
  BOTTOM w0.4: J2.B5 109.38,11.16 109.79,11.57 109.79,14.98 v1(106.44,18.33) ; v1(94.07,21.63) 91.87,23.83 91.87,29.07 92.23,29.43 93.42,29.43 93.79,29.06 C38.1
CLK: length 13.5
  BOTTOM w0.25: 109.48,30.42 107.12,30.42 105.54,32.01 102.97,32.01 102.17,31.21 U4.2
  BOTTOM w0.4: 109.48,30.42 109.85,30.05 109.85,28.06 J4.4
D: length 7.6
  BOTTOM w0.4: FL6.1 76.95,7.54 73.22,7.54 73.21,7.55 72.54,7.55 72.49,7.6 R34.1
  vias: v1(82.28,6.19) v1(82.28,5.19) v1(82.28,4.19) v1(82.28,3.19) v1(83.28,6.19) v1(83.28,5.19) v1(83.28,4.19) v1(83.28,3.19) v1(84.28,6.19) v1(84.28,5.19) v1(84.28,4.19) v1(84.28,3.19) v1(85.28,6.19) v1(85.28,5.19) v1(85.28,4.19) v1(85.28,3.19)
D+_1: length 3.5
  TOP w0.25: J1.A6 107.54,47.91 107.69,47.76 J1.B7 ; J1.A7 107.54,48.41 107.69,48.56 J1.B6
  TOP w0.508: J1.B7 J1.B6
D+_2: length 3.5
  TOP w0.25: J2.A7 107.74,10.61 107.89,10.76 J2.B6 J2.B7 107.89,9.96 107.74,10.11 J2.A6
D_2245090: length 7.1
  BOTTOM w0.508: R9.1 72.41,37.02 72.59,36.84 75.14,36.84 76.03,35.95 FL3.1
  vias: v1(81.67,36.29) v1(81.67,35.29) v1(81.67,34.29) v1(81.67,33.29) v1(82.67,36.29) v1(82.67,35.29) v1(82.67,34.29) v1(82.67,33.29) v1(83.67,36.29) v1(83.67,35.29) v1(83.67,34.29) v1(83.67,33.29) v1(84.67,36.29) v1(84.67,35.29) v1(84.67,34.29) v1(84.67,33.29)
DEBUG_1: length 5.3
  BOTTOM w0.25: U4.16 98.31,23.2 98.89,22.62 TP7.1
DEBUG_2: length 5.7
  BOTTOM w0.25: TP8.1 97.81,23.37 U4.17
DEBUG_3: length 3
  BOTTOM w0.25: TP9.1 97.31,25.44 U4.18
DEBUG_4: length 4.9
  BOTTOM w0.25: U4.30 93.54,31.71 TP10.1
IO: length 18.6
  BOTTOM w0.25: U4.1 101.93,31.71 102.83,32.61 107.2,32.61 107.53,32.94 109.38,32.94
  BOTTOM w0.4: J4.5 110.58,26.25 110.58,31.74 109.38,32.94
POW1: length 70.8
  TOP w0.4: C17.1 45.59,27.78 FL4.1 ; FL1.1 45.04,56.22 45.53,56.71 C1.1
  BOTTOM w0.508: R35.2 39.24,2.16 34.11,7.29 34.11,20.22 36.25,22.35 ; 33.36,32.38 33.41,32.33 R10.2
RTN1: length 45.8
  TOP w0.25: J1.A12 107.59,50.91 J1.B1 ; 105.58,45.41 J1.A1
  TOP w0.4: 105.58,45.41 105.57,45.41 105.14,44.99 105.14,43.17 106.53,41.78 110.01,41.78 111.58,40.21 111.58,27.79 109.15,25.36 107.13,25.36 106.26,26.23 v1(106.26,27.78)
  TOP w0.7: 72.52,59.97 73.74,59.97 74.3,59.41 74.3,57.73 73.27,56.71 71.38,56.71
  BOTTOM w0.4: C36.2 106.25,29.57 106.26,29.56 ; v1(106.26,27.78) C37.2
  BOTTOM w0.508: Q7.1 101.22,57.55 v1(99.91,57.55) ; Q5.1 94.74,57.25 R24.2 94.6,58.21 v1(94.57,58.23)
  vias: v1(104.3,52.3) v1(104.3,51.3) v1(105.3,52.3) v1(105.3,51.3)
RTN2: length 101.5
  TOP w0.25: J2.A1 107.79,7.61 J2.B12 ; J2.B1 107.79,13.11 J2.A12
  TOP w0.7: 110.58,13.1 110.58,18.68 113.49,21.59 113.49,39.88 110.93,42.44 110.93,51.44 110.74,51.63 110.74,58.02 107.29,61.47 72.36,61.47
  BOTTOM w0.4: C38.2 C39.2 v1(92.73,24.27)
  BOTTOM w0.508: Q8.1 99.31,18.9 99.12,18.71 v1(99.12,18.66) ; v1(94.12,18.74) 94.09,18.77 R25.2 93.17,17.83 Q6.1 ; C42.2 102.37,12.64 102.53,12.49 v1(104.28,12.49)
  vias: v1(104.28,13.49) v1(105.28,13.49) v1(105.28,12.49)
VSEL_1_P1: length 23.8
  TOP w0.4: v1(95.49,32.81) 101.35,32.81 v1(102.98,31.18)
  BOTTOM w0.25: v1(102.98,31.18) 102.98,31.02 102.66,30.71 U4.3
  BOTTOM w0.4: v1(95.49,32.81) 90,38.3 90,42.84 R14.1
VSEL_1_P2: length 23.4
  TOP w0.4: v1(102.98,30.22) 102.8,30.22 100.95,32.07 95,32.07 93.23,30.3 91.5,30.3 91.5,30.29 v1(90.89,30.29)
  BOTTOM w0.25: v1(102.98,30.22) 102.97,30.21 U4.4
  BOTTOM w0.4: v1(90.89,30.29) 90.38,29.79 90.38,23.49 R39.1
VTARG: length 4.8
  TOP w0.508: J3.2 108.44,37.71 108.44,35.92 108.45,35.9 J4.1
XRES: length 9.3
  BOTTOM w0.25: U4.10 101.86,27.21 102.95,26.12 C35.1
  BOTTOM w0.4: J4.3 107.12,27.86 107.12,26.71 106.53,26.12 R43.2 104.75,26.12 104.74,26.12 C35.1
N2276765: length 7.5
  BOTTOM w0.4: U1.14 52.19,38.49
  BOTTOM w0.45: 52.19,38.49 C16.1
  BOTTOM w0.508: C16.1 50.84,38.02 R11.2 49.43,36.11 VR1.2
N2494768: length 34
  TOP w0.508: v2(35.22,47.57) 36.05,47.57 36.06,47.57 C14.1
  BOTTOM w0.508: Q2.3 43.98,38.81 43.2,38.04 R7.1 ; R7.1 R6.1 ; R7.1 36.97,38.04 35.22,39.79 v2(35.22,47.57)
  BOTTOM w0.8: T1.1 45.43,48.76 C14.1
N2642535: length 2
  BOTTOM w0.508: Q2.2 46.15,38.02 R11.1
N2666518: length 5.4
  BOTTOM w0.4: R9.2 71.34,38.44 70.61,39.17 70.61,39.17 68.32,41.47 67.25,41.47 U1.7
N2729570: length 31.9
  TOP w0.508: v1(75.52,42.28) 75.52,33.42 77.33,31.61 v1(86.93,31.61)
  BOTTOM w0.4: U1.5 68.98,42.99 69.68,42.28 v1(75.52,42.28)
  BOTTOM w0.508: Q1.4 87.07,32.86 87.43,32.51 87.43,31.79 87.26,31.61 v1(86.93,31.61)
N2736973: length 24.4
  BOTTOM w0.25: 78.24,45.2 78.22,45.19 75.75,45.19 75.73,45.2 74.63,45.2 R12.2 ; 69.02,44.49 69.19,44.65 72.2,44.65 C15.1
  BOTTOM w0.35: U1.3 69.02,44.49
  BOTTOM w0.508: R12.2 74.48,45.06 C15.1 ; R14.2 88.13,46.55 87.34,46.55 86.7,45.91 R5.2 86.47,45.91 85.71,46.68 85.69,46.68 85.28,47.08 R3.2 84.54,46.01 84.31,45.79 78.83,45.79 78.24,45.2
N2742169: length 5.9
  BOTTOM w0.508: R7.2 42.76,39.87 45.43,39.87 45.85,39.45 Q2.1 46.31,39.74 VR2.1
N2993205: length 4.1
  BOTTOM w0.508: R6.2 44.74,34.8 45.83,35.88 VR1.1
N2996861: length 2.1
  BOTTOM w0.508: R5.1 86.36,44.3 C5.2
N4181205: length 9.4
  BOTTOM w0.508: R10.1 45.84,31.21 51.82,31.21 R13.2
N4181233: length 2.8
  BOTTOM w0.4: R13.1 53.12,37.2 53.66,37.74 U1.13
N11315036: length 4.3
  BOTTOM w0.508: Q4.4 95.01,9.74 R17.2 94.96,11.42 R20.1
N11315198: length 2.7
  BOTTOM w0.508: R20.2 95.34,15.78 95.35,15.79 Q6.3
N11315244: length 3.1
  BOTTOM w0.508: Q8.3 102.11,17.43 102.42,17.12 102.42,16.61 102.44,16.58 R21.2
N11315300: length 1.8
  BOTTOM w0.508: R23.2 92.33,15.96 Q6.2
N11318075: length 4.2
  BOTTOM w0.508: R18.1 95.95,50.3 R16.2 95.98,48.83 Q3.4
N11318137: length 2.8
  BOTTOM w0.508: R19.2 102.98,55.92 102.82,56.08 102.82,56.9 Q7.3
N11318145: length 2.4
  BOTTOM w0.508: Q5.3 96.34,54.47 96.35,54.46 R18.2
N11318201: length 1.7
  BOTTOM w0.508: R22.2 93.23,54.63 Q5.2
N11323189: length 35.9
  TOP w0.508: C27.1 42.47,19.6 v2(40.04,19.6)
  BOTTOM w0.508: R32.1 37.58,7.8 35.49,9.88 35.49,18.48 36.62,19.6 v2(40.04,19.6) ; R32.1 43.59,7.8 44.21,8.42 Q10.3 ; R32.1 42.33,6.84 42.33,6.84 R31.1
  BOTTOM w0.8: C27.1 45.34,18.61 46.4,18.61 46.48,18.53 T2.1
N11323517: length 2.5
  BOTTOM w0.508: R30.1 86.73,15.38 85.96,14.61 C21.2
N11323661: length 25.4
  BOTTOM w0.25: C28.1 72.84,14.49 72.65,14.31 69.65,14.31 69.61,14.27 ; 78.14,14.77 75.85,14.77 75.57,14.49 R38.2
  BOTTOM w0.3: U2.3 69.41,14.22 69.45,14.27 69.61,14.27
  BOTTOM w0.508: R38.2 72.89,14.49 C28.1 ; 78.14,14.77 79.47,16.1 84.29,16.1 84.61,16.42 R28.2 86.19,17.42 R30.2 86.88,16.8 87.64,17.57 87.76,17.57 R39.2
N11323821: length 33.8
  TOP w0.508: v1(89.42,2.38) 88.83,1.8 78.04,1.8 75.94,3.9 v1(75.94,12.12)
  BOTTOM w0.3: U2.5 68.89,12.72 69.51,12.11 75.24,12.11 75.25,12.12 v1(75.94,12.12)
  BOTTOM w0.508: Q9.4 88.85,2.94 v1(89.42,2.38)
N11323873: length 4.2
  BOTTOM w0.508: VR3.1 45.98,5.44 45.05,4.51 44.31,4.51 44.3,4.51 R31.2
N11323885: length 6.2
  BOTTOM w0.508: VR4.1 46.62,9.43 Q10.1 45.73,9.58 42.91,9.58 42.55,9.22 R32.2
N11323925: length 5.3
  BOTTOM w0.3: R34.2 70.67,9.03 70.41,9.29 70.41,9.33 68.51,11.22 U2.7
N11323959: length 1.9
  BOTTOM w0.508: R37.1 46.38,7.62 Q10.2
N11324073: length 7.2
  BOTTOM w0.4: C29.1 52.87,8.36 53,8.22 U2.14
  BOTTOM w0.508: C29.1 51.04,7.62 R37.2 49.54,5.62 VR3.2
N11324349: length 3
  BOTTOM w0.4: R36.1 53.83,7.47 U2.13
N11338172: length 8.2
  BOTTOM w0.508: R35.1 44.78,2.16 45.63,1.31 50.97,1.31 R36.2
N11773410: length 104
  TOP w0.7: 58.06,61.32 58.06,60.33 58.37,60.02 60.63,60.02 ; 58.06,61.32 57.58,61.8 14.43,61.8 TP2.1 ; 58.06,61.32 58.22,61.47 60.68,61.47
  BOTTOM w0.7: 60.78,60.38 59,60.38 58.72,60.66 58.72,61.57 ; 13.64,59.87 15.34,61.57 58.72,61.57 ; 60.73,61.82 58.98,61.82 58.72,61.57
N11791704: length 6.2
  BOTTOM w0.25: R41.2 100.04,25.31 99.81,25.54 U4.13
  BOTTOM w0.508: R41.2 99.81,24.22 99.81,23.33 100.08,23.06 R42.1 102.29,23.06 C34.1
N11792407: length 5.7
  BOTTOM w0.25: C40.1 99.34,34.06 99.31,34.04 U4.37
  BOTTOM w0.508: C40.1 99.5,34.68 R45.1 102.46,34.68 R44.2
N11794782: length 2.5
  BOTTOM w0.25: U4.33 97.31,33.98 97.22,34.08 C33.1
N11809700: length 3.4
  BOTTOM w0.3: C11.2 69.31,43.58 69.25,43.64 69.23,43.64 69.2,43.67 69.17,43.67 69.1,43.74 U1.4
N11811366: length 3.6
  BOTTOM w0.3: U2.4 69.47,13.47 69.7,13.24 C25.2

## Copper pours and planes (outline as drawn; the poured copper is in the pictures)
GND on BOTTOM (solid shape): 86.81,33.93 85.9,33.93 85.9,36.85 86.81,36.85
GND on BOTTOM (solid shape): 87.86,4.01 86.94,4.01 86.94,6.93 87.86,6.93
GND on TOP: 96.12,31.39 96.12,27.42 96.47,27.08 101.04,27.08 101.1,27.14 101.1,31.31 100.77,31.64 96.38,31.64
GND on TOP: 90.46,44.39 89.62,45.23 89.62,48.12 87.06,50.69 85.96,50.69 85.63,50.36 85.63,32.99 85.96,32.66 87.34,32.66 87.59,32.92 87.59,35.71 88.35,36.47 88.35,36.5 93.91,42.05 95.36,42.05 96.12,42.82 96.12,44.24 95.97,44.39
GND on TOP: 105.03,23.83 105.03,32.67 101.79,35.91 101.79,36.16 101.92,36.29 102.12,36.29 107.3,31.11 108.85,31.11 109.08,31.34 109.08,32.07 108.77,32.38 107.15,32.38 102.35,37.18 102.35,37.71 101.89,38.17 100.54,38.17 100.14,37.76 100.14,35.81 103.64,32.3 103.64,30.01 103.24,29.61 102.7,29.61 100.85,31.46 100.47,31.46 100.29,31.28 100.29,27.17 100.37,27.09 102.55,27.09 103.34,26.31 103.34,21.68 103.35,21.67 103.35,21.11 103.62,20.85 104.96,20.85 105.27,21.15 105.27,23.59
GND on TOP: 88.39,3.95 90.28,3.95 90.54,4.21 90.54,7.61 88.06,10.09 88.06,10.13 87.69,10.5 87.69,20.62 87.29,21.02 86.24,21.02 85.94,20.72 85.94,9.55 88.02,7.47 88.02,4.32
GND on BOTTOM: 97.27,38.19 101.84,38.19 102.02,38.02 102.02,36.64 101.92,36.54 100.59,36.54 100.16,36.97 95.03,36.97 94.93,37.08 94.93,37.81 95.59,38.47 95.59,40.76 95.31,41.04 93.43,41.04 93.18,41.29 93.18,44.11 93.48,44.42 96.15,44.42 96.81,43.76 96.81,38.65
GND on BOTTOM: 69.07,19.5 73.52,23.94 86.98,23.94 88.17,25.14 88.17,25.15 88.34,25.31 88.34,33.56 87.87,34.03 86.14,34.03 85.98,34.19 85.98,36.9 87.06,37.97 87.06,39.87 85.68,41.24 85.68,42.46 85.84,42.61 87.62,42.61 89.37,40.86 89.37,23.28 87.89,21.81 87.89,19.88 87.34,19.32 86.09,19.32 85.74,19.68 85.74,21.4 85.33,21.81 79.97,21.81 78.19,20.03 78.19,15.94 77.89,15.64 72.1,15.64 71.26,14.8 66.61,14.8 66.61,15.13 66.63,15.16 68.34,15.16 69.07,15.89
GND on BOTTOM: 103.54,20.9 103.69,20.74 105.37,20.74 105.55,20.92 105.55,23.54 105.24,23.84 103.85,23.84 103.54,23.54
GND on BOTTOM: 66.51,45.43 66.51,45.1 66.56,45.05 68.54,45.05 68.76,45.27 71.09,45.27 71.92,46.09 74.84,46.09 74.85,46.11 77.95,46.11 77.95,50.12 79.44,51.6 85.18,51.6 85.56,51.22 85.56,49.55 85.79,49.32 87.64,49.32 88,49.67 88,53.08 87.06,54.02 73.54,54.02 69.05,49.52 69.05,46.14 68.34,45.43
GND on BOTTOM: 87.01,6.82 87.01,4.06 87.18,3.88 90.66,3.88 91.04,4.27 91.04,10.3 88.48,12.87 86.35,12.87 86.12,12.64 86.12,11.65 87.72,10.05 87.72,7.54
GND1 on TOP: 50.07,46.88 45.73,46.88 44.54,45.69 28.24,45.69 26.95,44.4 26.95,18.24 27.3,17.88 30.35,17.88 30.73,18.26 30.73,21.56 30.94,21.77 31.22,21.77 31.43,21.55 31.43,6.13 36.7,0.86 57.53,0.86 58,1.33 58,13.1 57.68,13.42 55.01,13.42 51.62,16.81 45.6,16.81 44.85,16.05 39.47,16.05 35,20.52 35,25.12 42.05,32.17 57.26,32.17 57.82,32.73 57.82,42.46 57.44,42.84 54.11,42.84
GND1 on BOTTOM: 55.66,9.71 55.54,9.83 50.63,9.83 49.87,9.07 49.49,9.07 49.41,9.15 49.41,9.94 49.19,10.16 38.06,10.16 36.99,11.23 36.99,17.96 37.61,18.57 40.72,18.57 41.19,19.04 41.19,20.08 44.46,23.35 46.77,23.35 46.77,22 46.59,21.82 44.97,21.82 44.82,21.67 44.82,20.35 44.66,20.2 44.54,20.2 42.94,18.6 42.94,17.07 45.43,14.58 48.25,14.58 48.4,14.74 48.4,14.81 48.22,14.99 45.76,14.99 45.17,15.58 45.17,16.51 45.48,16.82 49.62,16.82 51.04,15.4 51.04,13.47 51.88,12.63 57.64,12.63 58,12.27 58,1.17 57.59,0.77 55.99,0.77 55.66,1.1
GND1 on BOTTOM: 55.66,32.2 55.56,32.3 55.56,39.75 55.33,39.98 50.31,39.98 49.72,39.39 49.41,39.39 49.19,39.62 49.19,40.4 49.06,40.53 37.84,40.53 37.15,41.22 37.15,48.16 37.76,48.77 39.87,48.77 44.64,53.54 46.42,53.54 46.42,52.19 46.24,52.01 44.61,52.01 44.46,51.86 44.46,50.54 42.71,48.79 42.71,47.26 45.38,44.59 48.35,44.59 48.47,44.72 48.47,44.92 48.35,45.05 45.45,45.05 45.01,45.5 45.01,46.28 45.76,47.03 49.54,47.03 50.96,45.61 50.96,43.68 51.67,42.98 57.28,42.98 57.77,42.49 57.77,32.68 57.29,32.2
VBUS_IN_1 on TOP: 77.53,39.72 82.15,39.72 83.42,40.99 83.42,51.86 83.67,52.1 87.83,52.1 90.53,49.41 90.53,45.49 91.04,44.98 92.47,44.98 92.72,45.23 92.72,51.45 89.47,54.7 81.27,54.7 80.6,54.04 80.6,43.45 79.72,42.56 77.58,42.56 76.87,41.85 76.87,40.38
VBUS_IN_1 on BOTTOM: 98.26,47.59 98.26,44.95 98.09,44.78 92.71,44.78 92.39,44.47 92.39,42.84 92.03,42.49 92.03,40.33 91.88,40.17 90.99,40.17 90.87,40.3 90.87,46.75 91.12,47.01 96.56,47.01 96.73,47.19 96.73,47.57 96.96,47.79 98.05,47.79
VBUS_IN_2 on TOP: 77.63,11.78 77.63,10.02 78.12,9.54 82.84,9.54 83.75,10.46 83.75,22.12 84.08,22.45 87.72,22.45 88.73,21.43 88.73,11.87 92.37,8.23 93.74,8.23 94.04,8.53 94.04,9.87 90.71,13.19 90.71,21.94 88.35,24.3 81.62,24.3 80.88,23.56 80.88,12.77 80.27,12.16 78.01,12.16
VBUS_IN_2 on BOTTOM: 97.34,8.68 97.34,5.74 97.06,5.46 92.29,5.46 91.88,5.86 91.88,9.9 92.09,10.1 93.76,10.1 94.04,9.82 94.04,8.22 94.24,8.02 95.51,8.02 95.69,8.2 95.69,8.53 95.84,8.68
VBUS_OUT_1 on BOTTOM (solid shape): 72.79,59.89 69.79,59.89 71.79,60.39 69.79,60.89 72.79,60.89
VBUS_OUT_1 on TOP: 105.57,49.83 105.57,48.51 105.29,48.23 104.68,48.23 103.67,47.22 103.67,42.29 103.08,41.71 99.35,41.71 98.74,42.32 98.74,49.58 99.27,50.11 105.29,50.11
VBUS_OUT_1 on BOTTOM: 107.17,45.84 107.17,49.55 106.75,49.97 100.61,49.97 100.34,50.23 100.34,54.74 100.14,54.94 99.2,54.94 98.99,54.74 98.99,42.14 99.45,41.68 105.74,41.68 105.84,41.78 105.84,41.9 105.34,42.39 105.34,44.01
VBUS_OUT_2 on BOTTOM (solid shape): 72.79,61.21 69.79,61.21 71.79,61.71 69.79,62.21 72.79,62.21
VBUS_OUT_2 on TOP: 105.12,11.71 96.62,11.71 95.99,11.07 95.99,2.97 96.34,2.62 104.84,2.62 105.52,3.3 105.52,9.02 105.22,9.32 104.73,9.32 104.43,9.63 104.43,10.87 104.68,11.13 105.04,11.13 105.22,11.3 105.22,11.61
VBUS_OUT_2 on BOTTOM: 98.36,15.76 98.36,3.07 98.82,2.62 104.84,2.62 105.75,3.53 105.75,6.55 107.45,8.25 107.45,11.7 107.33,11.83 106.61,11.83 106.53,11.74 106.53,10.69 105.4,9.56 104.65,9.56 104.4,9.8 104.4,10.71 104.79,11.09 104.99,11.09 105.19,11.3 105.19,11.68 105.14,11.73 104.51,11.73 103.58,10.8 100.02,10.8 99.76,11.07 99.76,15.93 98.53,15.93
D on BOTTOM (solid shape): 85.9,2.74 81.86,2.74 81.86,6.96 85.9,6.96
D on TOP: 77.13,6.68 77.89,7.44 85.56,7.44 85.91,7.09 85.91,3.2 85.48,2.77 78.75,2.77 77.13,4.39
D on BOTTOM: 85.91,7.26 85.91,0.87 85.7,0.66 69.8,0.66 69.29,1.17 69.29,7.11 69.96,7.79 81.21,7.79 81.29,7.87 81.29,9.54 81.32,9.57 82.31,9.57 82.38,9.49 82.38,7.84 82.66,7.56 85.61,7.56
D_2245090 on BOTTOM (solid shape): 84.86,32.66 80.82,32.66 80.82,36.88 84.86,36.88
D_2245090 on TOP: 77.43,37.46 84.5,37.46 85,36.96 85,33.09 84.57,32.66 77.81,32.66 76.52,33.95 76.52,36.54
D_2245090 on BOTTOM: 80.33,37.36 80.45,37.48 80.45,39.54 80.53,39.62 81.52,39.62 81.7,39.44 81.7,37.53 81.95,37.28 84.85,37.28 84.99,37.14 84.99,31.11 84.71,30.84 69.85,30.84 69.32,31.37 69.32,36.93 69.75,37.36
POW1 on TOP: 24.49,5.82 25.93,4.37 28.52,4.37 28.6,4.29 28.6,2.74 24.26,2.74 22.23,4.78 22.23,23.7 22.5,23.98 24.08,23.98 24.49,23.57
POW1 on BOTTOM: 29.17,51.17 34.71,56.71 46.14,56.71 46.57,57.14 46.57,59.2 46.75,59.38 48.22,59.38 48.3,59.3 48.3,55.39 48.19,55.29 41.06,55.29 39.71,53.93 39.71,51.45 38.85,50.59 35.52,50.59 33.53,48.6 33.53,32.84 33.88,32.49 33.88,32.13 33.53,31.78 33.53,31.24 34.34,30.43 41.17,30.43 45.16,26.44 45.16,26.43 46.49,26.43 46.67,26.61 46.67,28.74 46.8,28.87 48.07,28.87 48.14,28.8 48.14,25.44 47.76,25.06 40.73,25.06 39.56,23.89 39.56,22.06 38.82,21.33 35.47,21.33 34.59,20.45 34.32,20.45 34.28,20.48 34.28,24.55 32.54,26.29 28.19,26.29 26.64,24.74 26.64,23.04 25.65,22.05 22.68,22.05 22.15,22.58 22.15,28.37 29.17,35.39
RTN1 on TOP (solid shape): 72.8,59.51 69.83,59.51 69.81,59.51 71.8,60.01 69.8,60.51 72.8,60.51
RTN1 on TOP (solid shape): 108.28,52.93 108.28,52.42 108.08,52.22 108.08,51.73 108.22,51.59 108.22,50.89 108.01,50.68 107.77,50.68 107.58,50.87 107.58,51.67 107.41,51.84 106.41,51.84 105.86,52.4 105.86,52.98 106.15,53.27 107.94,53.27
RTN1 on TOP (solid shape): 108.21,45.41 108.21,44.71 108.13,44.63 108.13,44.19 108.27,44.05 108.27,43.42 107.91,43.06 106.23,43.06 105.91,43.38 105.91,44.1 106.42,44.61 107.24,44.61 107.56,44.93 107.57,44.95 107.57,45.43 107.76,45.62 108,45.62
RTN1 on TOP (solid shape): 105.73,51.3 110.01,51.3 110.16,51.15 110.16,45.15 109.93,44.92 107.73,44.92 107.4,45.25 106.03,45.25 106.03,45.56 106.06,45.58 108.16,45.58 108.42,45.33 109.31,45.33 109.41,45.43 109.41,50.77 109.15,51.02 108.34,51.02 108.09,50.77 104.71,50.77 104.35,51.12 104.35,51.48 105.55,51.48
RTN1 on BOTTOM (solid shape): 108.21,45.41 108.21,44.71 108.13,44.63 108.13,44.19 108.27,44.05 108.27,43.42 107.91,43.06 106.23,43.06 105.91,43.38 105.91,44.1 106.42,44.61 107.24,44.61 107.57,44.94 107.57,45.42 107.77,45.62 108,45.62
RTN1 on BOTTOM (solid shape): 108.28,52.93 108.28,52.42 108.08,52.22 108.08,51.73 108.22,51.59 108.22,50.89 108.01,50.68 107.77,50.68 107.58,50.87 107.58,51.67 107.41,51.84 106.4,51.84 105.85,52.4 105.85,52.98 106.14,53.27 107.94,53.27
RTN1 on TOP: 88.94,57.52 88.94,56.66 89.47,56.13 90.61,56.13 91.73,57.25 102.57,57.25 102.86,56.96 102.86,51.53 103.62,50.77 105.7,50.77 105.73,50.79 105.73,51.3 105.52,51.5 105.52,58.03 104.34,59.22 90.63,59.22
RTN1 on BOTTOM: 106.11,29.68 106.11,27.6 106.18,27.53 106.39,27.53 106.59,27.73 106.59,29.61 106.41,29.79 106.21,29.79
RTN1 on BOTTOM: 105.17,52.85 105.55,52.47 105.55,50.97 105.24,50.66 101.38,50.66 101.15,50.89 101.15,52.57 101.43,52.85
RTN1 on BOTTOM: 66.66,45.84 67.9,45.84 68.13,46.07 68.13,49.8 74.06,55.73 90.02,55.73 90.59,56.3 90.59,57.65 90.14,58.09 72.48,58.09 72.46,58.11 71.38,58.11 70.78,57.5 70.78,55.01 66.66,50.89
RTN2 on TOP (solid shape): 72.77,60.98 69.8,60.98 69.78,60.99 71.77,61.49 69.77,61.99 72.77,61.99
RTN2 on TOP (solid shape): 108.48,15.12 108.48,14.61 108.28,14.41 108.28,13.93 108.42,13.79 108.42,13.09 108.21,12.88 107.97,12.88 107.78,13.07 107.78,13.87 107.61,14.04 106.61,14.04 106.06,14.59 106.06,15.17 106.35,15.46 108.14,15.46
RTN2 on TOP (solid shape): 108.41,7.61 108.41,6.91 108.33,6.83 108.33,6.39 108.47,6.25 108.47,5.62 108.11,5.26 106.43,5.26 106.11,5.58 106.11,6.3 106.62,6.81 107.44,6.81 107.76,7.13 107.77,7.15 107.77,7.63 107.96,7.82 108.2,7.82
RTN2 on TOP (solid shape): 105.85,13.71 107.71,13.71 107.81,13.81 108.21,13.81 108.49,13.53 110.68,13.53 110.98,13.23 110.98,7.26 110.81,7.08 108.57,7.08 108.37,6.88 107.91,6.88 107.76,7.03 107.76,7.28 107.61,7.44 106.31,7.44 106.23,7.51 106.23,7.74 108.37,7.74 108.57,7.54 109.41,7.54 109.61,7.74 109.61,12.95 109.38,13.18 108.52,13.18 108.32,12.97 108.32,12.95 105.93,12.95 105.7,12.72 105.7,12.26 105.55,12.11 104.12,12.11 103.97,12.26 103.97,13.96 104.08,14.07 105.5,14.07
RTN2 on BOTTOM (solid shape): 108.41,7.61 108.41,6.91 108.33,6.83 108.33,6.39 108.47,6.25 108.47,5.62 108.11,5.26 106.43,5.26 106.11,5.58 106.11,6.3 106.62,6.81 107.44,6.81 107.77,7.14 107.77,7.62 107.97,7.82 108.2,7.82
RTN2 on BOTTOM (solid shape): 108.48,15.12 108.48,14.61 108.28,14.41 108.28,13.93 108.42,13.79 108.42,13.09 108.21,12.88 107.97,12.88 107.78,13.07 107.78,13.87 107.61,14.04 106.6,14.04 106.05,14.59 106.05,15.17 106.34,15.46 108.14,15.46
RTN2 on TOP: 85.71,25.39 88.15,25.39 91.64,21.9 91.64,16.56 96.1,12.11 105.55,12.11 105.65,12.21 105.65,13.91 105.5,14.06 99.53,14.06 97.9,15.69 97.9,16.81 99.43,18.33 99.43,18.76 99.24,18.95 94.52,18.95 93.33,20.14 93.33,24.1 92.85,24.58 91.35,24.58 88.33,27.6 85.51,27.6 85.13,27.22 85.13,25.98
RTN2 on BOTTOM: 68.08,19.85 73.65,25.42 86.6,25.42 86.8,25.62 86.8,27.22 86.42,27.6 73.72,27.6 72.7,28.63 71.55,28.63 71.15,28.22 71.15,25.04 69.96,23.85 69.94,23.85 66.69,20.6 66.69,15.82 66.94,15.56 67.96,15.56 68.08,15.69
RTN2 on BOTTOM: 105.27,13.91 105.5,13.68 105.5,12.34 105.32,12.16 103.9,12.16 103.31,11.57 101.1,11.57 100.82,11.85 100.82,13.56 101.18,13.91
N2239928 on BOTTOM: 55.1,45.84 53.73,45.84 53.6,45.97 53.6,49.01 55.33,50.74 57.39,50.74 57.49,50.64 57.49,50.16 57.24,49.9 55.87,49.9 55.1,49.14
N2254675 on BOTTOM: 50.28,59.12 50.28,55.64 50.53,55.39 53.96,55.39 53.99,55.41 53.99,56.63 53.83,56.79 51.75,56.79 51.42,57.12 51.42,59.07 51.24,59.25 50.4,59.25
N2722737 on BOTTOM: 82.74,39.59 82.74,38.65 82.84,38.55 86.07,38.55 86.09,38.57 86.09,39.54 85.99,39.64 82.79,39.64
N2725054 on BOTTOM: 52.36,51.63 52.36,51 51.8,50.44 48.4,50.44 48.4,53.41 48.5,53.51 49.69,53.51 49.9,53.31 49.9,52.19 50.12,51.96 52.03,51.96
N2741729 on BOTTOM: 56.12,56.76 56.12,52.32 56.27,52.16 57.26,52.16 57.39,52.29 57.39,56.74 57.29,56.84 56.2,56.84
N11323399 on BOTTOM: 55.98,19.83 57.14,19.83 57.34,20.03 57.34,20.46 57.16,20.64 55.34,20.64 53.53,18.83 53.53,15.63 53.58,15.58 55.08,15.58 55.15,15.65 55.15,19
N11323505 on BOTTOM: 83.5,9.54 83.5,8.65 83.6,8.55 86.68,8.55 86.78,8.65 86.78,9.62 83.58,9.62
N11323551 on BOTTOM: 50.18,28.87 50.18,25.44 50.43,25.19 53.78,25.19 53.91,25.32 53.91,26.33 53.71,26.53 51.8,26.53 51.57,26.76 51.57,28.8 51.37,29 50.3,29
N11323577 on BOTTOM: 48.73,23.02 48.73,20.38 48.85,20.25 52.21,20.25 52.54,20.58 52.54,21.59 52.28,21.85 50.4,21.85 49.97,22.28 49.97,23.02 49.79,23.2 48.91,23.2
N11323649 on BOTTOM: 55.97,26.45 55.97,21.9 56.17,21.7 57.06,21.7 57.26,21.9 57.26,26.47 57.11,26.62 56.14,26.62
N11773410 on TOP (solid shape): 63.26,61.98 61.27,61.48 63.26,60.98 60.27,60.98 60.27,61.99 63.26,61.99
N11773410 on TOP (solid shape): 63.26,60.51 61.27,60.01 63.26,59.51 60.27,59.51 60.27,60.51 63.26,60.51
N11773410 on BOTTOM (solid shape): 61.3,61.7 63.3,61.2 60.3,61.2 60.3,62.2 63.3,62.2
N11773410 on BOTTOM (solid shape): 61.3,60.38 63.3,59.88 60.3,59.88 60.3,60.88 63.3,60.88
N11773410 on BOTTOM: 11.28,60.05 11.28,55.17 11.79,54.66 15.42,54.66 16.59,55.83 16.59,59 18.85,61.26 18.85,61.77 18.82,61.8 13.03,61.8
N11773414 on BOTTOM: 3.73,61.37 0.91,61.37 0.51,60.96 0.51,55.17 1.31,54.37 3.75,54.37 4.65,55.27 4.65,60.45
N11773458 on BOTTOM: 11.79,51.44 11.13,50.77 11.13,44.4 12.99,42.53 12.99,25.13 14.4,23.72 14.4,15.01 15.14,14.27 16.08,14.27 16.92,15.11 16.92,50.32 15.8,51.44
N11773490 on BOTTOM: 9.37,14.33 10.41,15.37 10.41,22.63 7.98,25.07 7.98,33.35 7.8,33.53 4.09,33.53 2.69,32.13 2.69,24.59 5.71,21.56 5.71,15.19 6.58,14.33
N11773520 on BOTTOM: 25.37,12.9 28.19,12.9 28.68,13.39 28.68,14.43 28.14,14.96 24.28,14.96 14.43,5.11 14.43,4.22 14.88,3.76 16.23,3.76
N11773524 on BOTTOM: 8.48,5.82 11.99,2.31 19.79,2.31 19.82,2.35 21.86,2.35 22.66,3.15 22.66,6.83 25.55,9.73 28.22,9.73 28.57,9.37 28.57,8.15 28.04,7.62 26.42,7.62 24.82,6.02 24.82,1.85 23.37,0.41 10.54,0.41 6.81,4.14 6.81,5.26 7.37,5.82
N11800517 on BOTTOM: 0.51,50.71 0.51,42.24 3.91,38.84 7.42,38.84 7.87,39.29 7.87,40.41 3.94,44.35 3.94,50.47 3.16,51.24 1.04,51.24
N27250240 on BOTTOM: 47.48,51.25 45.22,51.25 45.15,51.17 45.15,50.54 45.22,50.46 47.58,50.46 47.61,50.49 47.61,51.12
N113238491 on BOTTOM: 45.6,20.93 47.71,20.93 47.81,20.83 47.81,20.27 47.76,20.22 45.63,20.22 45.55,20.3 45.55,20.88

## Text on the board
Ref Des/Silkscreen Bottom: TM | IO | GND | CLK | XRES | Vtarg | InnoSwitch -3 CP
Ref Des/Silkscreen Top: N | L | RTN2 | RTN1 | Debug4 | VBUS_IN2 | VBUS_IN1 | Debug2 | Debug3 | Debug1 | 1729 | S/N | DER-551 RevB
PLACE_BOUND_BOTTOM: 7 SLOTS | 14.  FAB HOUSE LOGO,DATE CODE TO BE IN SILK SCREEN ONLY.DO NOT USE COPPER. | 13.  MATERIAL FR4 COPPER 2oz THICKNESS 0.062"
PAGE_OUTLINE: FIGURE | FINISHED_SIZE | 12.0 | 18.0 | 20.0 | 30.0 | 40.0 | 46.0 | 50.0 | 52.0 | 67.0 | 68.0 | 35.433x16.0 | 65.0x26.0 | 38.0x30.0 | DRILL CHART: TOP to BOTTOM | ALL UNITS ARE IN MILS | ROTATION | - | 90.000 | 0.000 | PLATED | NON-PLATED | QTY | 268 | 20 | 6 | 18 | 25 | 1 | 36 | 8 | 2 | 4
